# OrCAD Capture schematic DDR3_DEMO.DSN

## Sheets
1 01 POWER: size C; title: MCIMX6Q-SMART DEVICE; rev: A1; company: Freescale Semiconductor; note: SOURCE:SCH-27392 PDF:SPF-27392; note: 6501 William Cannon Drive West; note: Austin, TX 78735-8598
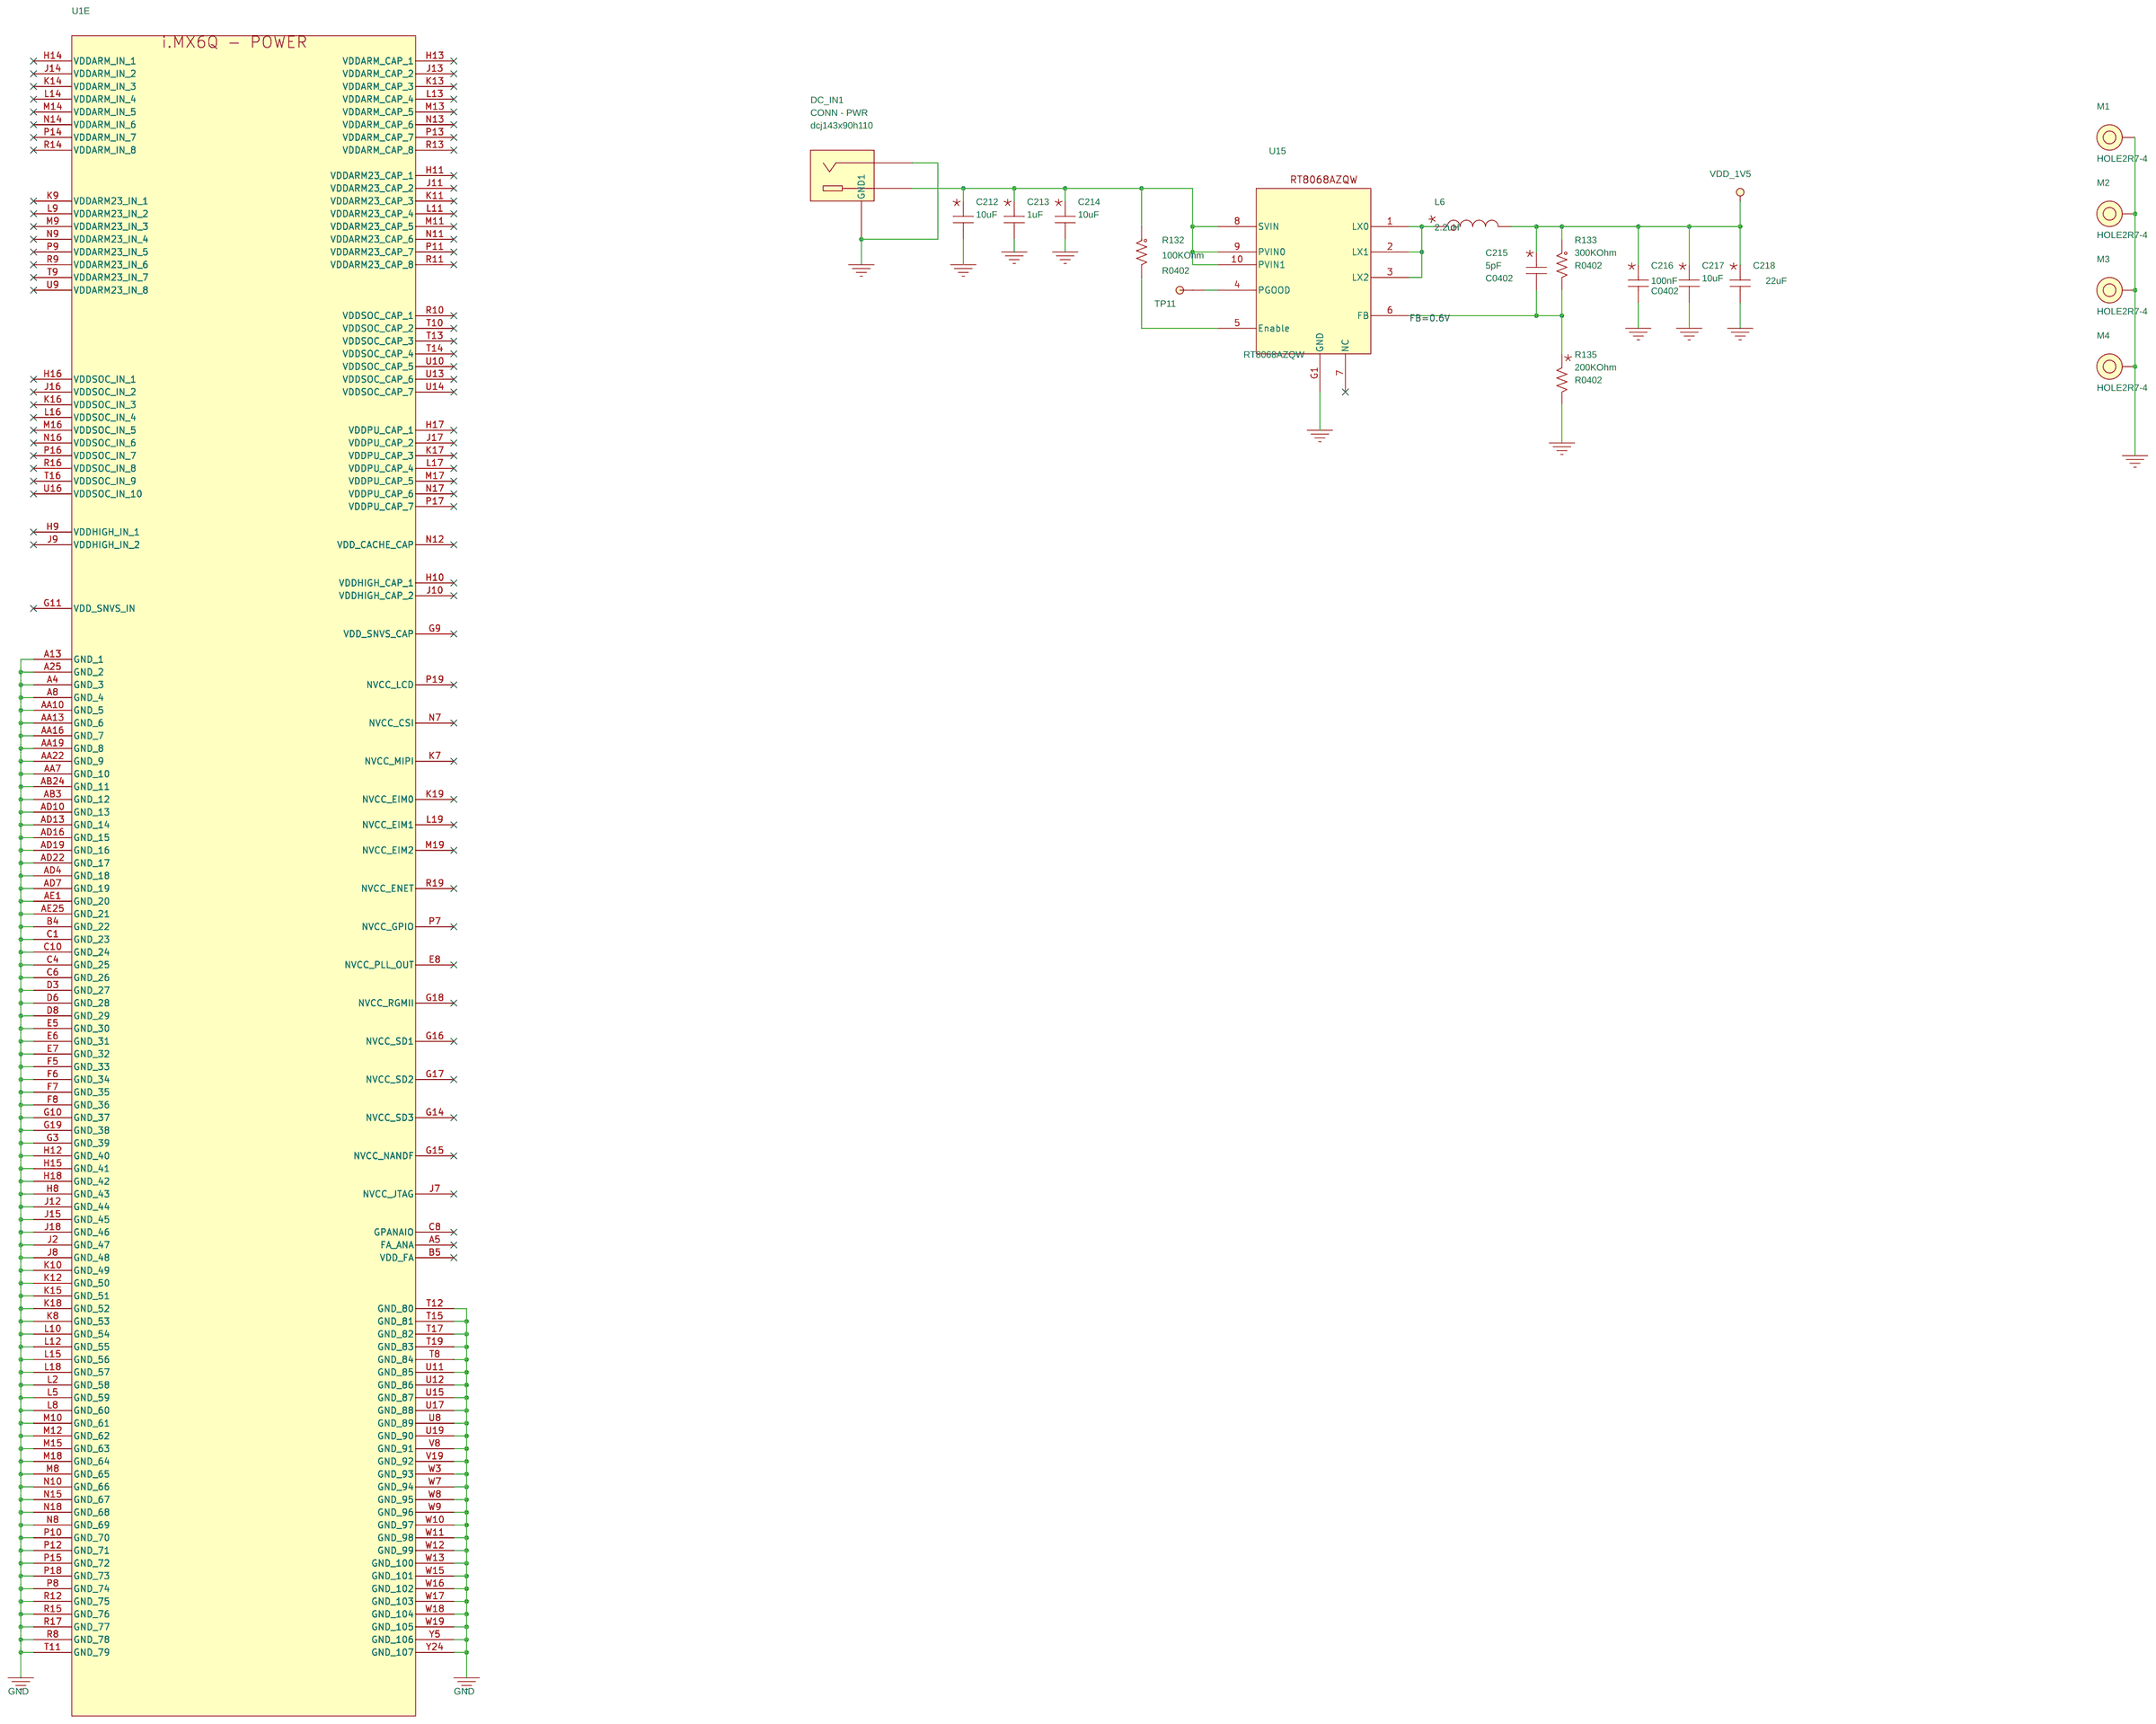
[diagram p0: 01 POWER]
2 02 DDR3 MEMORY: size C; rev: B1
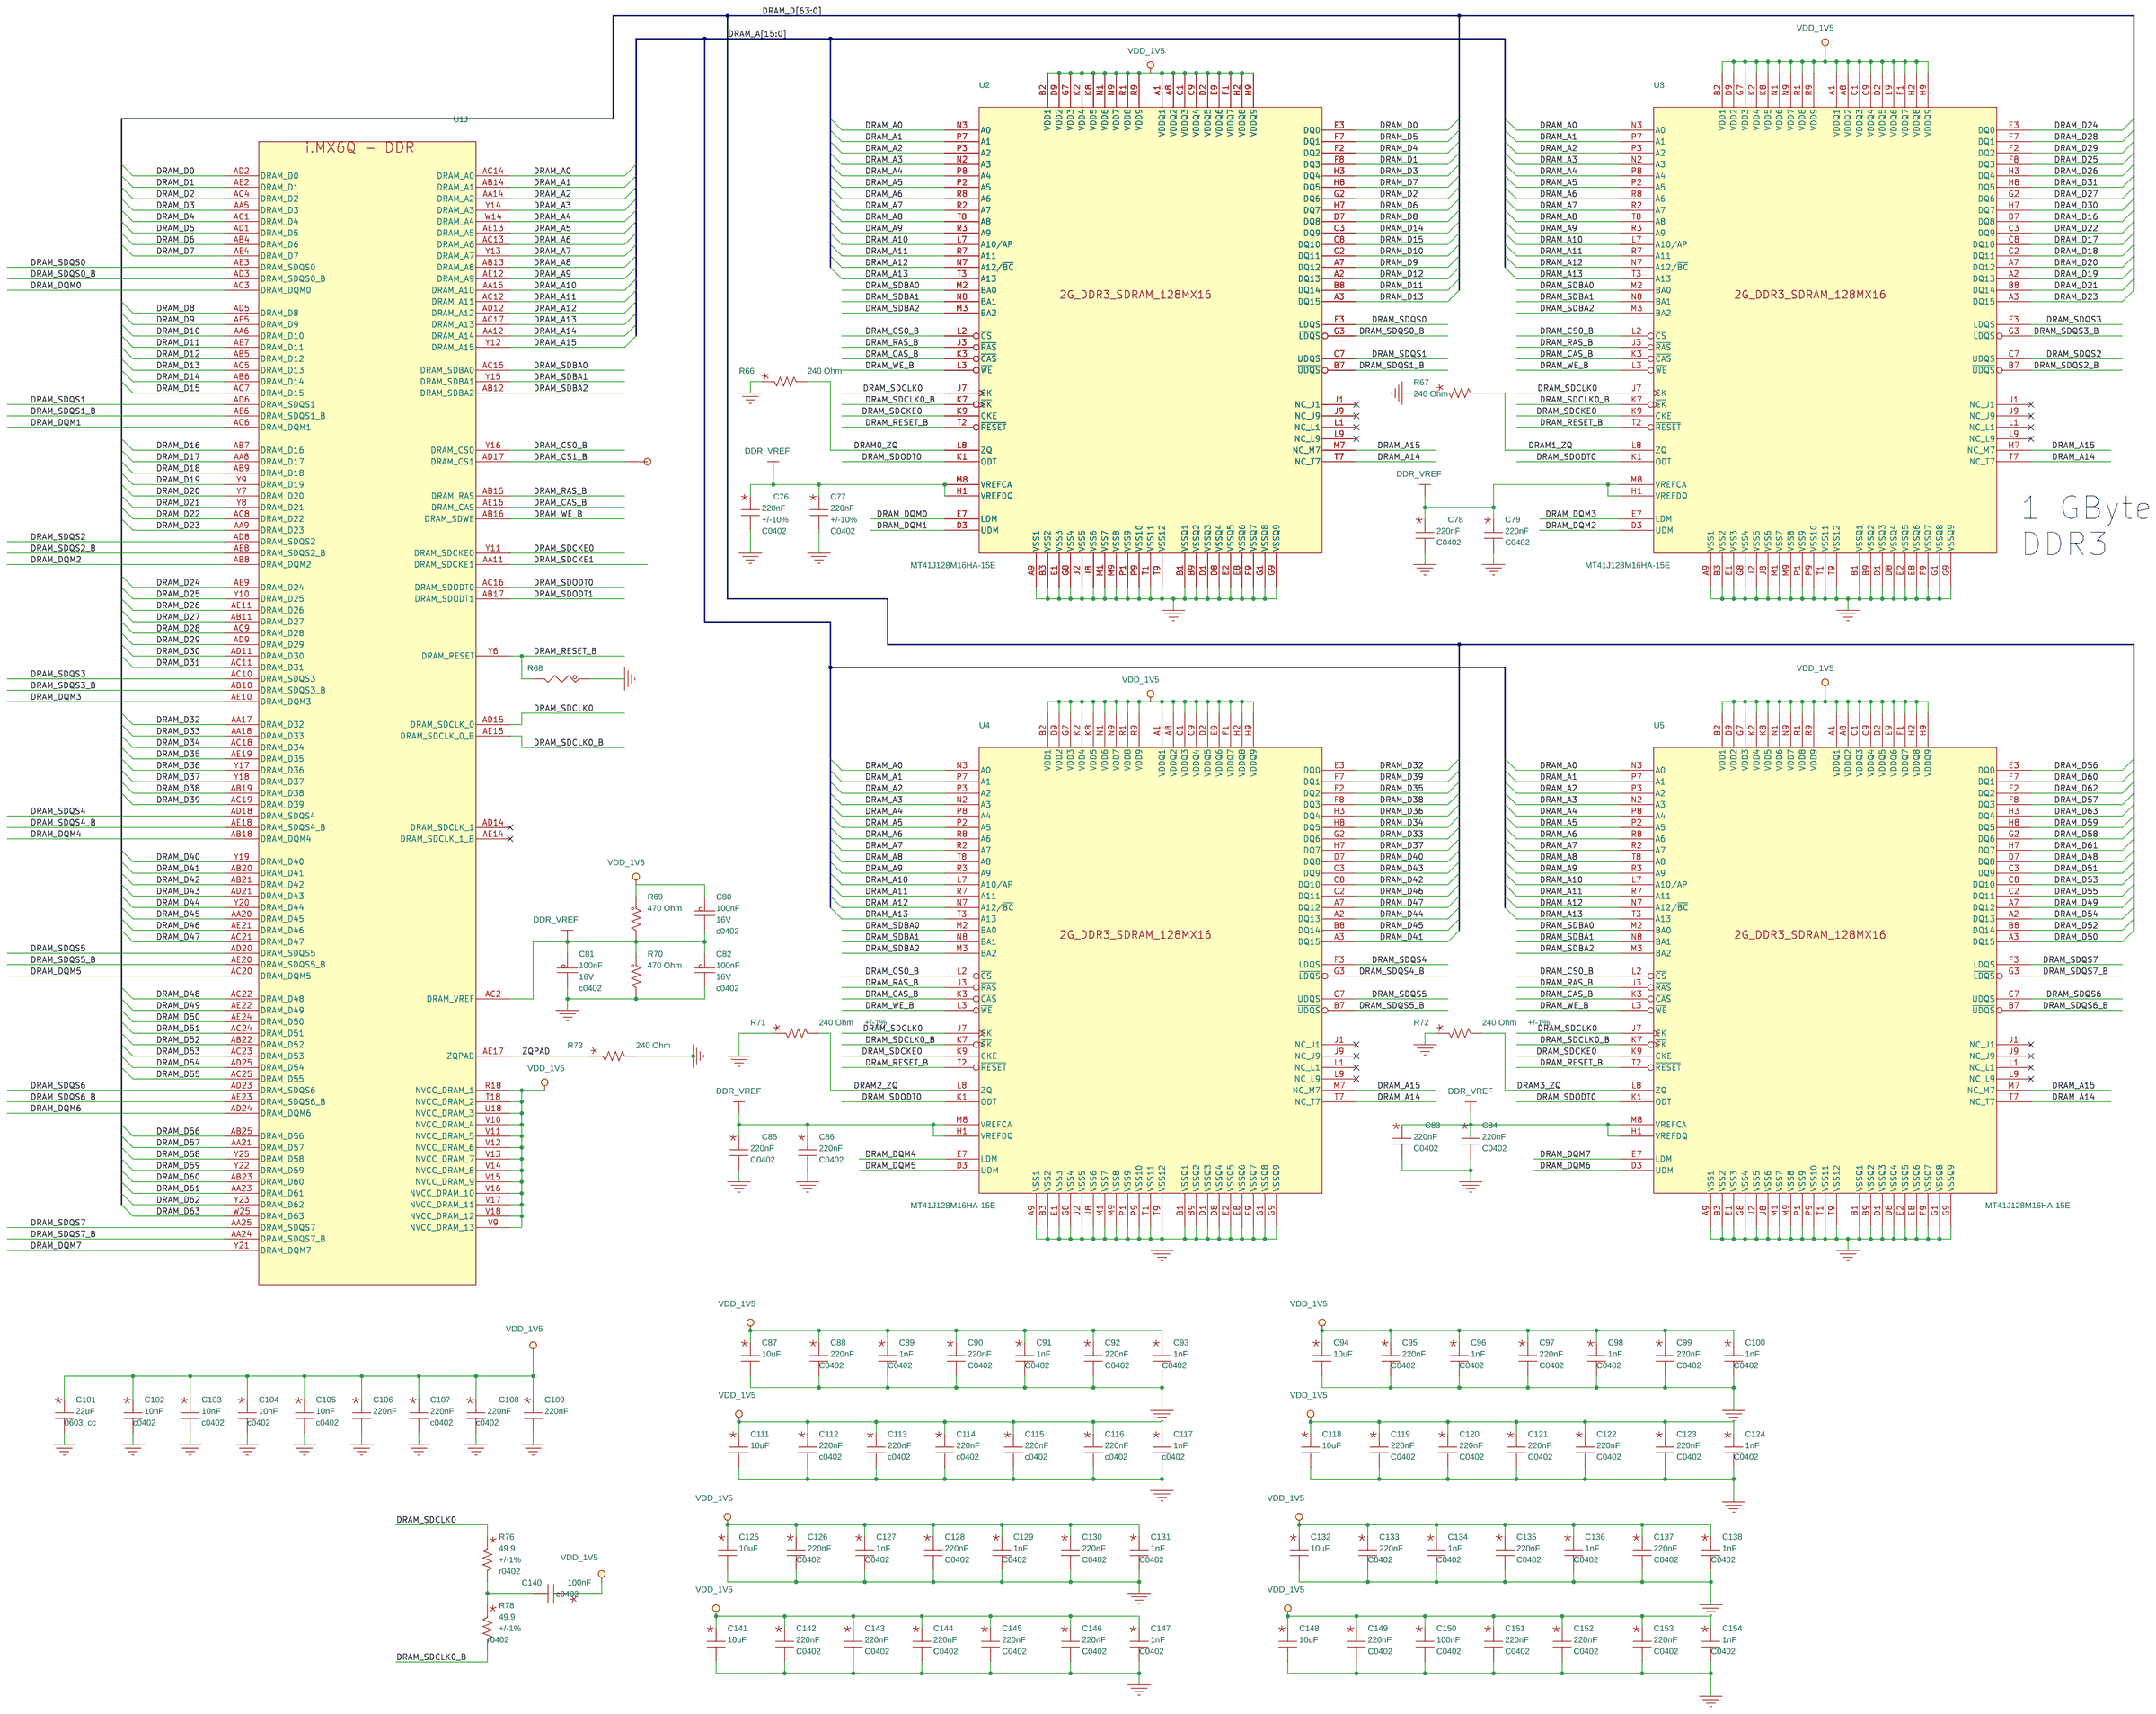
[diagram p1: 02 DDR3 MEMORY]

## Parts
sheet 01 POWER
C212  10uF  [c0603]
C213  1uF  [c0402]
C214  10uF  [c0603]
C215  5pF  [C0402]
C216  100nF  [C0402]
C217  10uF  [c0603]
C218  22uF  [c0805]
DC_IN1  CONN - PWR  [dcj143x90h110]
L6  2.2uH  [l2_5r0x5r0_lqh]
M1  HOLE2R7-4  [HOLE2R7-4]
M2  HOLE2R7-4  [HOLE2R7-4]
M3  HOLE2R7-4  [HOLE2R7-4]
M4  HOLE2R7-4  [HOLE2R7-4]
R132  100KOhm  [R0402]
R133  300KOhm  [R0402]
R135  200KOhm  [R0402]
TP11  TP  [TPC30B]
U1  iMX6Q  [BGA624_0P8_21X21]  (sections E,J)
U15  RT8068AZQW  [dfn11ch8]
sheet 02 DDR3 MEMORY
C76  220nF  [C0402]
C77  220nF  [C0402]
C78  220nF  [C0402]
C79  220nF  [C0402]
C80  100nF  [c0402]
C81  100nF  [c0402]
C82  100nF  [c0402]
C83  220nF  [C0402]
C84  220nF  [C0402]
C85  220nF  [C0402]
C86  220nF  [C0402]
C87  10uF  [c0603]
C88  220nF  [C0402]
C89  1nF  [C0402]
C90  220nF  [C0402]
C91  1nF  [C0402]
C92  220nF  [C0402]
C93  1nF  [C0402]
C94  10uF  [c0603]
C95  220nF  [C0402]
C96  1nF  [C0402]
C97  220nF  [C0402]
C98  1nF  [C0402]
C99  220nF  [C0402]
C100  1nF  [C0402]
C101  22uF  [0603_cc]
C102  10nF  [c0402]
C103  10nF  [c0402]
C104  10nF  [c0402]
C105  10nF  [c0402]
C106  220nF  [c0402]
C107  220nF  [c0402]
C108  220nF  [c0402]
C109  220nF  [c0402]
C111  10uF  [c0402]
C112  220nF  [c0402]
C113  220nF  [c0402]
C114  220nF  [c0402]
C115  220nF  [c0402]
C116  220nF  [c0402]
C117  1nF  [c0402]
C118  10uF  [c0603]
C119  220nF  [C0402]
C120  220nF  [C0402]
C121  220nF  [C0402]
C122  220nF  [C0402]
C123  220nF  [C0402]
C124  1nF  [C0402]
C125  10uF  [c0603]
C126  220nF  [C0402]
C127  1nF  [C0402]
C128  220nF  [C0402]
C129  1nF  [C0402]
C130  220nF  [C0402]
C131  1nF  [C0402]
C132  10uF  [c0603]
C133  220nF  [C0402]
C134  1nF  [C0402]
C135  220nF  [C0402]
C136  1nF  [C0402]
C137  220nF  [C0402]
C138  1nF  [C0402]
C140  100nF  [c0402]
C141  10uF  [c0603]
C142  220nF  [C0402]
C143  220nF  [C0402]
C144  220nF  [C0402]
C145  220nF  [C0402]
C146  220nF  [C0402]
C147  1nF  [C0402]
C148  10uF  [c0603]
C149  220nF  [C0402]
C150  100nF  [C0402]
C151  220nF  [C0402]
C152  220nF  [C0402]
C153  220nF  [C0402]
C154  1nF  [C0402]
R66  240 Ohm  [r0402]
R67  240 Ohm  [r0402]
R68  10K  [r0402]
R69  470 Ohm  [r0402]
R70  470 Ohm  [r0402]
R71  240 Ohm  [r0402]
R72  240 Ohm  [r0402]
R73  240 Ohm  [r0402]
R76  49.9  [r0402]
R78  49.9  [r0402]
TP2  TP  [TPC30B]
U2  MT41J128M16HA-15E  [bga96_0p8_9p15x14p15]
U3  MT41J128M16HA-15E  [bga96_0p8_9p15x14p15]
U4  MT41J128M16HA-15E  [bga96_0p8_9p15x14p15]
U5  MT41J128M16HA-15E  [bga96_0p8_9p15x14p15]

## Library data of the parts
C87 C94 C118 C125 C132 C141 C148 C212 C217 C218 = CC0603MRX5R5BB106: CAP,10uF,+/-20%,X5R,10V,G,SMD0603; Approval Status: E; CCL: for MID; DATASHEET_NUMBER: 55612; Foxconn Part Number: 620112400-023-G; Green State: G; HHPN: STDPN; Item Status : E; Mfg: TAIYO; Mfg Part Number: LMK107BJ106MALTD; ONLY_DATASHEETNAME: YAGEO_CC0603MRX5R5BB106_DS.pdf; Package Type: SMD; Package Type : SMD; Part Number: 62010L000-011-G; Part Type: RoHS\Capacitor\MLCC; RELATED_PARTS: http://ytpdm.efoxconn.com/Windchill/netmarkets/jsp/ext/ytpdm/bom/cis/searchManufacturePart1.jsp?strVPartNumber=62010L000-VPN-G; Relex Category: 4; Relex Subcategory: 3; Remark: Reserved; Sub System: Reserved; Supplier P/N : LMK107BJ106MALTD; Tolerance: 6.3V,X5R,+/-20%; VPN: 620112400-VPN-G
C213 = CAP: CAP,1uF,+/-10%,X5R,10V,G,SMD0402; Approval Status: E; CCL: G; Foxconn Part Number: 62010JJ00-015-G; HHPN: 62-01020084-00-015; Item Status : E; KEYID: 20050721-82649; Mfg: MURATA; Mfg Part Number: GRM155R61A105K; ONLY_DATASHEETNAME: MURATA_GRM155R60J105KE19D_DS.pdf; PCB_FOOTPRINT_BEFORE: c0402h5; Package Type: SMD; Package Type : SMD; Part Number: 62-01020084-00-015; Part Type: RoHS\Capacitor\MLCC; RELATED_PARTS: http://ytpdm.efoxconn.com/Windchill/netmarkets/jsp/ext/ytpdm/bom/cis/searchManufacturePart1.jsp?strVPartNumber=62010BN00-VPN-G; Relex Category: 4; Relex Subcategory: 1; Remark: Reserved; Sub System: Reserved; Supplier P/N : GRM155R61A105K; Tolerance: 6.3V,X5R,+/-10%; VPN: 62010JJ00-VPN-G
C214 = GRM188R60J475K: CAP,4.7uF,+/-10%,X5R,6.3V,G,SMD0603; Approval Status: A; CCL: LF; CD: 5; CR6: 5; Foxconn Part Number: 62010BP00-015-G; Green State: C5; HG: 5; HHPN: 62-01020086-00-015; Item Status : A; Mfg: MURATA; ONLY_DATASHEETNAME: MURATA_GRM188R60J475K_DS.pdf; PB: 5; PBB: 5; PBDE: 5; PCB_FOOTPRINT_BEFORE: c0603h8; Package Type: SMD; Package Type : SMD; Part Number: 62-01020086-00-015; Part Type: VPN\ROHS\Capacitor\MLCC; RELATED_PARTS: http://ytpdm.efoxconn.com/Windchill/netmarkets/jsp/ext/ytpdm/bom/cis/searchManufacturePart1.jsp?strVPartNumber=62010BP00-VPN-G; Relex Category: 4; Relex Subcategory: 1; Remark: Reserved; Sub System: Reserved; Tolerance: +/-10%; VPN: 62010BP00-VPN-G; Value : 4.7uF
C215 = CAP: CAP,5pF,+/-0.25pF,NPO(C0G),25V,G,SMD0201; Approval Status: E; CCL: G; DATASHEET_NUMBER: 0000159154; Foxconn Part Number: 62011SB00-015-G; Green State: G; HHPN: STDPN; Item Status : E; KEYID: 20070118-16031; Mfg: MURATA; Mfg Part Number: GRM0335C1E5R0CD01D; ONLY_DATASHEETNAME: MURATA_GRM1555C1H5R0C_DS.pdf; Package Type: SMD; Package Type : SMD; Part Number: GRM1555C1H5R0C; Part Type: RoHS\Capacitor\MLCC; RELATED_PARTS: http://ytpdm.efoxconn.com/Windchill/netmarkets/jsp/ext/ytpdm/bom/cis/searchManufacturePart1.jsp?strVPartNumber=62010UD00-VPN-G; Relex Category: 4; Remark: Reserved; Sub System: Reserved; Supplier P/N : GRM0335C1E5R0CD01D; Tolerance: +/-0.25pF; VPN: 62011SB00-VPN-G
C216 = CAP: CAP,100nF,+/-10%,X5R,10V,G,SMD0201; Approval Status: A; CD: 100; CR6: 1000; Foxconn Part Number: 620112U00-011-G; Green State: C5; HG: 1000; HHPN: 62-01030380-00-011-G; Item Status : A; KEYID: 1667; Mfg: YAGEO; Mfg Part Number: CC0201KRX5R6BB104; ONLY_DATASHEETNAME: MLCC.pdf; PB: 1000; PBB: 1000; PBDE: 1000; Package Type: SMD; Package Type : SMD; Part Number: 62-01030380-00-011; Part Type: VPN\ROHS\Capacitor\MLCC; RELATED_PARTS: http://ytpdm.efoxconn.com/Windchill/netmarkets/jsp/ext/ytpdm/bom/cis/searchManufacturePart1.jsp?strVPartNumber=620101T00-VPN-G; Relex Category: 4; Relex Subcategory: 3; Remark: Reserved; Sub System: Reserved; Supplier P/N : CC0201KRX5R6BB104; Tolerance: 16V, X7R, +/-10%; VPN: 620112U00-VPN-G
DC_IN1 = JPD1021-NB751-7F_0: CONN,I/O,Power Jack,R/A,Bla,G/F,G,DIP-3; Approval Status: E; CCL: G; Foxconn Part Number: 340415U00-H59-G; Green State: G; HHPN: STDPN; Mfg: SINGATRON; Mfg Part Number: 2DC-G213I200; Only Datasheet Name: FOXCONN_JPD1021-NB751-7F_DS.pdf; Package Type: DIP; Part Number: 340415600-600-G; Part Type: RoHS\Connector\I/O Port; Relex Category: 9; Relex Subcategory: 1; Remark: @DCIN; Sub System: Reserved; Tolerance: <Tolerance>; VPN: 340415U00-H59-G; Datasheet: http://pdm-dmd.pdm.foxconn.com/cis/MB/Dell/Datasheet/FOXCONN_JPD1021-NB751-7F_DS.pdf
L6 = PCMB042T-2R2MS_0: IND,2.2uH@100KHz,+/-30%,2.6A,36mOhm,SHLD,G,SMD; Approval Status: E; CCL: for MID; DATASHEET_NUMBER: 55499; Foxconn Part Number: 63033K000-015-G; Green State: G; HHPN: STDPN; Item Status : E; Mfg: MURATA; Mfg Part Number: LQH5BPN2R2NT0L; ONLY_DATASHEETNAME: CYNTEC_PCMB042T-2R2MS_DS.pdf; Package Type: SMD; Package Type : SMD; Part Number: 63031HQ00-034-G; Part Type: RoHS\Inductor\SMD Power Inductor; RELATED_PARTS: http://ytpdm.efoxconn.com/Windchill/netmarkets/jsp/ext/ytpdm/bom/cis/searchManufacturePart1.jsp?strVPartNumber=63031HQ00-VPN-G; Relex Category: 5; Relex Subcategory: 2; Remark: Reserved; Sub System: Reserved; Supplier P/N : LQH5BPN2R2NT0L; Tolerance: +/-20%; VPN: 63033K000-VPN-G
M1-M4 = MNTHOLE_3.2
R132 = RC0201JR-07100KL: RES,100KOhm,+/-1%,1/20W,G,SMD0201; Approval Status: E; CCL: G; DATASHEET_NUMBER: 291759; Foxconn Part Number: 61011E300-011-G; Green State: G; HHPN: STDPN; Item Status : E; Mfg: YAGEO; Mfg Part Number: RC0201FR-07100KL; ONLY_DATASHEETNAME: YAGEO_RC0201JR-07100KL_DS.rar; Package Type: SMD; Package Type : SMD; Part Number: 61011ES00-011-G; Part Type: RoHS\Resistor\Chip Resistor; RELATED_PARTS: http://ytpdm.efoxconn.com/Windchill/netmarkets/jsp/ext/ytpdm/bom/cis/searchManufacturePart1.jsp?strVPartNumber=61011ES00-VPN-G; Relex Category: 3; Relex Subcategory: 2; Remark: Reserved; Sub System: Reserved; Supplier P/N : RC0201FR-07100KL; Tolerance: +/-1%
R133 = RC0402FR-07150KL: RES,300KOhm,+/-1%,1/20W,G,SMD0201; Approval Status: E; CCL: RoHS; CD: 100; CR6: 1000; DATASHEET_NUMBER: 81926; Foxconn Part Number: 61012W600-011-G; Green State: C5; HG: 1000; HHPN: 61-01002463-01-011; Item Status : E; KEYID: 20060609-111810; Mfg: YAGEO; Mfg Part Number: RC0201FR-07300KL; ONLY_DATASHEETNAME: YAGEO_RC0402FR_07150KL_DS.pdf; PB: 1000; PBB: 1000; PBDE: 1000; PCB_FOOTPRINT_BEFORE: r0402h4; Package Type: SMD; Package Type : SMD; Part Number: 61-01002463-01-011; Part Type: VPN\ROHS\Resistor\Chip Resistor; RELATED_PARTS: http://ytpdm.efoxconn.com/Windchill/netmarkets/jsp/ext/ytpdm/bom/cis/searchManufacturePart1.jsp?strVPartNumber=610116G00-VPN-G; Relex Category: 3; Relex Subcategory: 2; Remark: Reserved; Sub System: Reserved; Supplier P/N : RC0201FR-07300KL; Tolerance: +/-1%; VPN: 61012W600-VPN-G
R135 = RC0402FR-07100KL: RES,200KOhm,+/-1%,1/20W,G,SMD0201; Approval Status: E; CCL: G; CD: 100; CR6: 1000; Foxconn Part Number: 61011VW00-011-G; Green State: C5; HG: 1000; HHPN: 61-01000550-03-011-G; Item Status : E; KEYID: 20051019-14316; Mfg: YAGEO; Mfg Part Number: RC0201FR-07200KL; ONLY_DATASHEETNAME: YAGEO_RC0402FR_07100KL_DS.pdf; PB: 1000; PBB: 1000; PBDE: 1000; PCB_FOOTPRINT_BEFORE: r0402h4; Package Type: SMD; Package Type : SMD; Part Number: 61-01000550-03-011-G; Part Type: VPN\ROHS\Resistor\Chip Resistor; RELATED_PARTS: http://ytpdm.efoxconn.com/Windchill/netmarkets/jsp/ext/ytpdm/bom/cis/searchManufacturePart1.jsp?strVPartNumber=61010L100-VPN-G; Relex Category: 3; Relex Subcategory: 2; Remark: Reserved; Sub System: Reserved; Supplier P/N : RC0201FR-07200KL; Tolerance: +/-1%; VPN: 61011VW00-VPN-G
TP2 TP11 = TP_0: TEST POINT; Critical_Part: No; Part Number: Waiting Foxconn Part Number; QVL_Approve: None; Remark: Dummy; Vendor: Waiting
U1 = PCIMX6Q6VV1A_0: IC MCU MX6QUAD ARM CORTEX-A9 FCLBGA624; AGILE_PN: 344-01218; CAD_APPROVED: Yes; HEIGHT: 2.16MM; MFG_NAME01: FREESCALE SEMICONDUCTOR; MFG_PN01: PCIMX6Q0AVT01A; ROHS: Yes
U15 = RT9199PSP_5: IC,Regulator,RT8068AZQW,3A,1MHZ,G,WDFN-10,SMD; Approval Status: E; CCL: G; CD: 100; CR6: 1000; Foxconn Part Number: 32012EL00-264-G; Green State: C6; HG: 1000; HHPN: 32-09400062-00; Item Status : E; KEYID: 20060510-112323; Mfg: RICHTEK; ONLY_DATASHEETNAME: RICHTEK_RT9199PSP_DS.pdf; PB: 1000; PBB: 1000; PBDE: 1000; Package Type: SMD; Package Type : SMD; Part Number: 32-09400062-00; Part Type: ROHS\IC\Linear IC; RELATED_PARTS: http://ytpdm.efoxconn.com/Windchill/netmarkets/jsp/ext/ytpdm/bom/cis/searchManufacturePart1.jsp?strVPartNumber=320109Y00-VPN-G; Relex Category: 1; Relex Subcategory: 3; Remark: Reserved; Sub System: Reserved; VPN: 32012EL00-VPN-G
C76-C79 C83-C86 C109 = CAP: CAP,220nF,+/-20%,X5R,6.3V,G,SMD0201; Approval Status: A; CCL: G; CD: 100; CR6: 1000; DATASHEET_NUMBER: 0000175265; Foxconn Part Number: 620115S00-015-G; Green State: C5; HG: 1000; HHPN: STDPN; KEYID: 20070321-51853; Mfg: MURATA; Mfg Part Number: GRM033R60J224ME15D; ONLY_DATASHEETNAME: YAGEO_CC0603KRX7R7BB224_DS.pdf; PB: 1000; PBB: 1000; PBDE: 1000; Package Type: SMD; Part Number: 62010KD00-011-G; Part Type: VPN\ROHS\Capacitor\MLCC; RELATED_PARTS: http://ytpdm.efoxconn.com/Windchill/netmarkets/jsp/ext/ytpdm/bom/cis/searchManufacturePart1.jsp?strVPartNumber=62010KD00-VPN-G; Relex Category: 4; Relex Subcategory: 3; Remark: Reserved; Sub System: Reserved; Supplier : MURATA; Tolerance: +/-10%; VPN: 620115S00-VPN-G
C80-C82 = CAP_NP: CAP CER 0.1UF 16V 10% X7R 0402; AGILE_PN: 150-75182; CAD_APPROVED: Yes; FPLIST: CC0402_25,CC0402_HD,0402_CC; HEIGHT: 0.635MM; MFG_NAME01: KEMET; MFG_PN01: C0402C104K4RAC; PRIORITY_PN: 021-00274; ROHS: Yes; SIGNAL_MODEL: DEFAULT_CAPACITOR_100000pF_2_1; Tolerance: 10%; WVDC: 16V
C88 C92 C95 C99 C112 C115 C116 C119 C122 C123 C126 C130 C133 C137 C142 C145 C146 C149 C152 C153 = CAP: CAP,100nF,+/-10%,X5R,10V,G,SMD0201; Approval Status: A; CD: 100; CR6: 1000; Foxconn Part Number: 620112U00-011-G; Green State: C5; HG: 1000; HHPN: 62-01030380-00-011-G; KEYID: 1667; Mfg: YAGEO; Mfg Part Number: CC0201KRX5R6BB104; ONLY_DATASHEETNAME: MLCC.pdf; PB: 1000; PBB: 1000; PBDE: 1000; Package Type: SMD; Part Number: 62-01030380-00-011; Part Type: VPN\ROHS\Capacitor\MLCC; RELATED_PARTS: http://ytpdm.efoxconn.com/Windchill/netmarkets/jsp/ext/ytpdm/bom/cis/searchManufacturePart1.jsp?strVPartNumber=620101T00-VPN-G; Relex Category: 4; Relex Subcategory: 3; Remark: Reserved; Sub System: Reserved; Supplier : YAGEO; Tolerance: 16V, X7R, +/-10%; VPN: 620112U00-VPN-G
C89 C96 C127 C134 = CAP: CAP,1nF,+/-10%,X7R,25V,G,SMD0402; Approval Status: A; CD: 100; CR6: 1000; Foxconn Part Number: 62010LF00-011-G; Green State: C5; HG: 1000; HHPN: 62-01030114-00-011-G; KEYID: 1705; Mfg: YAGEO; Mfg Part Number: CC0201KRX7R8BB102; ONLY_DATASHEETNAME: MLCC.pdf; PB: 1000; PBB: 1000; PBDE: 1000; Package Type: SMD; Part Number: 62-01030114-00-011; Part Type: VPN\ROHS\Capacitor\MLCC; RELATED_PARTS: http://ytpdm.efoxconn.com/Windchill/netmarkets/jsp/ext/ytpdm/bom/cis/searchManufacturePart1.jsp?strVPartNumber=620103K00-VPN-G; Relex Category: 4; Relex Subcategory: 3; Remark: Reserved; Sub System: Reserved; Supplier : YAGEO; Tolerance: 50V, X7R, +/-10%; VPN: 62010LF00-VPN-G
C90 C97 C128 C135 = CAP: CAP,100nF,+/-10%,X5R,10V,G,SMD0201; Approval Status: A; CD: 100; CR6: 1000; Foxconn Part Number: 620112U00-011-G; Green State: C5; HG: 1000; HHPN: 62-01030380-00-011-G; KEYID: 1667; Mfg: YAGEO; Mfg Part Number: CC0201KRX5R6BB104; ONLY_DATASHEETNAME: MLCC.pdf; PB: 1000; PBB: 1000; PBDE: 1000; Package Type: SMD; Part Number: 62-01030380-00-011; Part Type: VPN\ROHS\Capacitor\MLCC; RELATED_PARTS: http://ytpdm.efoxconn.com/Windchill/netmarkets/jsp/ext/ytpdm/bom/cis/searchManufacturePart1.jsp?strVPartNumber=620101T00-VPN-G; Relex Category: 4; Relex Subcategory: 3; Remark: Dummy; Sub System: Rserved; Supplier : YAGEO; Tolerance: 16V, X7R, +/-10%; VPN: 620112U00-VPN-G
C91 C98 C129 C136 = CAP: CAP,1nF,+/-10%,X7R,25V,G,SMD0201; Approval Status: A; CD: 100; CR6: 1000; Foxconn Part Number: 62010LF00-011-G; Green State: C5; HG: 1000; HHPN: 62-01030114-00-011-G; Item Status : A; KEYID: 1705; Mfg: YAGEO; Mfg Part Number: CC0201KRX7R8BB102; ONLY_DATASHEETNAME: MLCC.pdf; PB: 1000; PBB: 1000; PBDE: 1000; Package Type: SMD; Package Type : SMD; Part Number: 62-01030114-00-011; Part Type: VPN\ROHS\Capacitor\MLCC; RELATED_PARTS: http://ytpdm.efoxconn.com/Windchill/netmarkets/jsp/ext/ytpdm/bom/cis/searchManufacturePart1.jsp?strVPartNumber=620103K00-VPN-G; Relex Category: 4; Relex Subcategory: 3; Remark: Reserved; Sub System: Rserved; Supplier P/N : CC0201KRX7R8BB102; Tolerance: 50V, X7R, +/-10%; VPN: 62010LF00-VPN-G
C93 C100 C117 C124 C131 C138 C147 C154 = CAP: CAP,1nF,+/-10%,X7R,25V,G,SMD0201; Approval Status: A; CD: 100; CR6: 1000; Foxconn Part Number: 62010LF00-011-G; Green State: C5; HG: 1000; HHPN: 62-01030114-00-011-G; KEYID: 1705; Mfg: YAGEO; Mfg Part Number: CC0201KRX7R8BB102; ONLY_DATASHEETNAME: MLCC.pdf; PB: 1000; PBB: 1000; PBDE: 1000; Package Type: SMD; Part Number: 62-01030114-00-011; Part Type: VPN\ROHS\Capacitor\MLCC; RELATED_PARTS: http://ytpdm.efoxconn.com/Windchill/netmarkets/jsp/ext/ytpdm/bom/cis/searchManufacturePart1.jsp?strVPartNumber=620103K00-VPN-G; Relex Category: 4; Relex Subcategory: 3; Remark: Reserved; Sub System: Reserved; Supplier : YAGEO; Tolerance: 50V, X7R, +/-10%; VPN: 62010LF00-VPN-G
C101 = CAP: CAP CER 22UF 4V 20% X5R 0603; Approval Status: A; CD: 5; CR6: 5; Foxconn Part Number: 620108H00-015-G; Green State: C5; HG: 5; HHPN: 62-01020059-00-015-G; Item Status : A; KEYID: 20050824-04221; Mfg: MURATA; Mfg Part Number: GRM21BR60J226M; ONLY_DATASHEETNAME: MURATA_GRM21BR60J226ME39L_DS.pdf; PB: 5; PBB: 5; PBDE: 5; PCB_FOOTPRINT_BEFORE: c0805h14; Package Type: SMD; Package Type : SMD; Part Number: 62-01020059-00-015; Part Type: VPN\ROHS\Capacitor\MLCC; RELATED_PARTS: http://ytpdm.efoxconn.com/Windchill/netmarkets/jsp/ext/ytpdm/bom/cis/searchManufacturePart1.jsp?strVPartNumber=620108H00-VPN-G; Relex Category: 4; Relex Subcategory: 1; Remark: Reserved; Sub System: Reserved; Supplier P/N : GRM21BR60J226M; Tolerance: 6.3V,X5R,+/-20%; VPN: 620108H00-VPN-G
C102 C103 = GRM155R71H103K: CAP,10nF,+/-10%,X7R,10V,G,SMD0201; Approval Status: E; CCL: G; DATASHEET_NUMBER: 0000246316; Footprint : C0201; Foxconn Part Number: 62010LA00-011-G; Green State: G; HHPN: STDPN; KEYID: 20071225-23718; Mfg: YAGEO; Mfg Part Number: CC0201KRX7R6BB103; ONLY_DATASHEETNAME: MURATA_GRM155R71H103K_DS.pdf; Package Type: SMD; Part Number: 62010QB00-015-G; Part Type: RoHS\Capacitor\MLCC; RELATED_PARTS: http://ytpdm.efoxconn.com/Windchill/netmarkets/jsp/ext/ytpdm/bom/cis/searchManufacturePart1.jsp?strVPartNumber=62010QB00-VPN-G; Relex Category: 4; Relex Subcategory: 2; Remark: Reserved; Sub System: Reserved; Supplier : YAGEO; Tolerance: +/-10%; VPN: 62010LA00-VPN-G
C104 = GRM155R71H103K: CAP,10nF,+/-10%,X7R,10V,G,SMD0201; Approval Status: E; CCL: G; DATASHEET_NUMBER: 0000246316; Footprint : C0201; Foxconn Part Number: 62010LA00-011-G; Green State: G; HHPN: STDPN; KEYID: 20071225-23718; Mfg: YAGEO; Mfg Part Number: CC0201KRX7R6BB103; ONLY_DATASHEETNAME: MURATA_GRM155R71H103K_DS.pdf; Package Type: SMD; Part Number: 62010QB00-015-G; Part Type: RoHS\Capacitor\MLCC; RELATED_PARTS: http://ytpdm.efoxconn.com/Windchill/netmarkets/jsp/ext/ytpdm/bom/cis/searchManufacturePart1.jsp?strVPartNumber=62010QB00-VPN-G; Relex Category: 4; Relex Subcategory: 2; Sub System: Reserved; Supplier : YAGEO; Tolerance: +/-10%; VPN: 62010LA00-VPN-G
C105 = GRM155R71H103K: CAP,10nF,+/-10%,X7R,10V,G,SMD0201; Approval Status: E; CCL: G; Footprint : C0201; Green State: G; HHPN: STDPN; Mfg: YAGEO; Mfg Part Number: CC0201KRX7R6BB103; ONLY_DATASHEETNAME: MURATA_GRM155R71H103K_DS.pdf; Package Type: SMD; Part Number: 62010QB00-015-G; Part Type: RoHS\Capacitor\MLCC; RELATED_PARTS: http://ytpdm.efoxconn.com/Windchill/netmarkets/jsp/ext/ytpdm/bom/cis/searchManufacturePart1.jsp?strVPartNumber=62010QB00-VPN-G; Relex Category: 4; Relex Subcategory: 2; Sub System: Reserved; Supplier : YAGEO; Tolerance: +/-10%
C106 = CAP: CAP,220nF,+/-20%,X5R,6.3V,G,SMD0201; Approval Status: A; CCL: G; CD: 100; CR6: 1000; DATASHEET_NUMBER: 0000175265; Foxconn Part Number: 620115S00-015-G; Green State: C5; HG: 1000; HHPN: STDPN; KEYID: 20070321-51853; Mfg: MURATA; Mfg Part Number: GRM033R60J224ME15D; ONLY_DATASHEETNAME: YAGEO_CC0603KRX7R7BB224_DS.pdf; PB: 1000; PBB: 1000; PBDE: 1000; Package Type: SMD; Part Number: 62010KD00-011-G; Part Type: VPN\ROHS\Capacitor\MLCC; RELATED_PARTS: http://ytpdm.efoxconn.com/Windchill/netmarkets/jsp/ext/ytpdm/bom/cis/searchManufacturePart1.jsp?strVPartNumber=62010KD00-VPN-G; Relex Category: 4; Relex Subcategory: 3; Sub System: Reserved; Supplier : MURATA; Tolerance: +/-10%; VPN: 620115S00-VPN-G
C107 C108 = CAP: CAP,220nF,+/-20%,X5R,6.3V,G,SMD0201; Approval Status: A; CCL: G; CD: 100; CR6: 1000; DATASHEET_NUMBER: 0000175265; Footprint : C0201; Foxconn Part Number: 620115S00-015-G; Green State: C5; HG: 1000; HHPN: STDPN; KEYID: 20070321-51853; Mfg: MURATA; Mfg Part Number: GRM033R60J224ME15D; ONLY_DATASHEETNAME: YAGEO_CC0603KRX7R7BB224_DS.pdf; PB: 1000; PBB: 1000; PBDE: 1000; Package Type: SMD; Part Number: 62010KD00-011-G; Part Type: VPN\ROHS\Capacitor\MLCC; RELATED_PARTS: http://ytpdm.efoxconn.com/Windchill/netmarkets/jsp/ext/ytpdm/bom/cis/searchManufacturePart1.jsp?strVPartNumber=62010KD00-VPN-G; Relex Category: 4; Relex Subcategory: 3; Remark: Reserved; Sub System: Reserved; Supplier : MURATA; Tolerance: +/-10%; VPN: 620115S00-VPN-G
C111 = CC0603MRX5R5BB106: CAP,10uF,+/-20%,X5R,10V,G,SMD0603; Approval Status: E; CCL: for MID; DATASHEET_NUMBER: 55612; Footprint : c0603; Foxconn Part Number: 620112400-023-G; Green State: G; HHPN: STDPN; Item Status : E; Mfg: TAIYO; Mfg Part Number: LMK107BJ106MALTD; ONLY_DATASHEETNAME: YAGEO_CC0603MRX5R5BB106_DS.pdf; Package Type: SMD; Package Type : SMD; Part Number: 62010L000-011-G; Part Type: RoHS\Capacitor\MLCC; RELATED_PARTS: http://ytpdm.efoxconn.com/Windchill/netmarkets/jsp/ext/ytpdm/bom/cis/searchManufacturePart1.jsp?strVPartNumber=62010L000-VPN-G; Relex Category: 4; Relex Subcategory: 3; Remark: Reserved; Sub System: Reserved; Supplier P/N : LMK107BJ106MALTD; Tolerance: 6.3V,X5R,+/-20%; VPN: 620112400-VPN-G
C113 C114 C120 C121 C143 C144 C150 C151 = CAP: CAP,100nF,+/-10%,X5R,10V,G,SMD0201; Approval Status: A; CD: 100; CR6: 1000; Foxconn Part Number: 620112U00-011-G; Green State: C5; HG: 1000; HHPN: 62-01030380-00-011-G; KEYID: 1667; Mfg: YAGEO; Mfg Part Number: CC0201KRX5R6BB104; ONLY_DATASHEETNAME: MLCC.pdf; PB: 1000; PBB: 1000; PBDE: 1000; Package Type: SMD; Part Number: 62-01030380-00-011; Part Type: VPN\ROHS\Capacitor\MLCC; RELATED_PARTS: http://ytpdm.efoxconn.com/Windchill/netmarkets/jsp/ext/ytpdm/bom/cis/searchManufacturePart1.jsp?strVPartNumber=620101T00-VPN-G; Relex Category: 4; Relex Subcategory: 3; Remark: Reserved; Sub System: Rserved; Supplier : YAGEO; Tolerance: 16V, X7R, +/-10%; VPN: 620112U00-VPN-G
C140 = CAP: CAP,100nF,+/-10%,X5R,10V,G,SMD0201; Approval Status: A; CD: 100; CR6: 1000; Footprint : C0201; Foxconn Part Number: 620112U00-011-G; Green State: C5; HG: 1000; HHPN: 62-01030380-00-011-G; Item Status : A; KEYID: 1667; Mfg: YAGEO; Mfg Part Number: CC0201KRX5R6BB104; ONLY_DATASHEETNAME: MLCC.pdf; PB: 1000; PBB: 1000; PBDE: 1000; Package Type: SMD; Package Type : SMD; Part Number: 62-01030380-00-011; Part Type: VPN\ROHS\Capacitor\MLCC; RELATED_PARTS: http://ytpdm.efoxconn.com/Windchill/netmarkets/jsp/ext/ytpdm/bom/cis/searchManufacturePart1.jsp?strVPartNumber=620101T00-VPN-G; Relex Category: 4; Relex Subcategory: 3; Remark: Reserved; Sub System: Reserved; Supplier P/N : CC0201KRX5R6BB104; Tolerance: 16V, X7R, +/-10%; VPN: 620112U00-VPN-G
R66 R67 R71-R73 = RC0402FR-07240RL: RES,240 Ohm,+/-1%,1/20W,G,SMD0201; Approval Status: E; CCL: G; CD: 2; CR6: 2; DATASHEET_NUMBER: 0000245957; Foxconn Part Number: 610135N00-011-G; Green State: C2; HG: 2; HHPN: STDPN; KEYID: 20071222-91056; Mfg: YAGEO; Mfg Part Number: RC0201FR-07240RL; ONLY_DATASHEETNAME: YAGEO_RC0402FR-07240RL_DS.pdf; PB: 230316.6; PBB: 5; PBDE: 5; Package Type: SMD; Part Number: 61011T800-011-G; Part Type: RoHS\Resistor\Chip Resistor; RELATED_PARTS: http://ytpdm.efoxconn.com/Windchill/netmarkets/jsp/ext/ytpdm/bom/cis/searchManufacturePart1.jsp?strVPartNumber=61011T800-VPN-G; Relex Category: 3; Relex Subcategory: 1; Remark: Reserved; Sub System: Reserved; Supplier : YAGEO; Tolerance: +/-1%; VPN: 610135N00-VPN-G
R68 = RES: RES MF 10.0K 1/16W 1% 0402; AGILE_PN: 470-75416; CAD_APPROVED: Yes; FPLIST: RC0402,rc0402_frs; MFG_NAME01: VISHAY INTERTECHNOLOGY; MFG_PN01: CRCW040210K0FKED; PRIORITY_PN: 006-00552; ROHS: Yes; ROOM: KEYPAD; SIGNAL_MODEL: DEFAULT_RESISTOR_10000OHM_2_1; Tolerance: 1%
R69 R70 = RC0603FR-07470RL: RES,470 Ohm,+/-1%,1/20W,G,SMD0201; Approval Status: E; CCL: LF; CD: 100; CR6: 1000; Foxconn Part Number: 61012RN00-011-G; Green State: C5; HG: 1000; HHPN: 61-01000377-01-011-G; Item Status : E; KEYID: 20060509-81844; Mfg: YAGEO; Mfg Part Number: RC0201FR-07470RL; ONLY_DATASHEETNAME: YAGEO_RC0603FR_07470RL_DS.pdf; PB: 230317; PBB: 1000; PBDE: 1000; PCB_FOOTPRINT_BEFORE: r0603h6; Package Type: SMD; Package Type : SMD; Part Number: 61-01000377-01-011; Part Type: VPN\ROHS\Resistor\Chip Resistor; RELATED_PARTS: http://ytpdm.efoxconn.com/Windchill/netmarkets/jsp/ext/ytpdm/bom/cis/searchManufacturePart1.jsp?strVPartNumber=610104E00-VPN-G; Relex Category: 3; Relex Subcategory: 2; Remark: Reserved; Sub System: Reserved; Supplier P/N : RC0201FR-07470RL; VPN: 61012RN00-VPN-G
R76 R78 = RC0402FR-0749R9L: RES,49.9Ohm,+/-1%,1/20W,G,SMD0201; Approval Status: E; CCL: LF; CD: 100; CR6: 1000; Foxconn Part Number: 61011EM00-011-G; Green State: C5; HG: 1000; HHPN: 61-01000833-02-011-G; Item Status : E; KEYID: 4987; Mfg: YAGEO; Mfg Part Number: RC0201FR-0749R9L; ONLY_DATASHEETNAME: YAGEO-RC0402FR-0749R9L-DS.pdf; PB: 1000; PBB: 1000; PBDE: 1000; Package Type: SMD; Package Type : SMD; Part Number: 61-01000833-02-011; Part Type: VPN\ROHS\Resistor\Chip Resistor; RELATED_PARTS: http://ytpdm.efoxconn.com/Windchill/netmarkets/jsp/ext/ytpdm/bom/cis/searchManufacturePart1.jsp?strVPartNumber=610102700-VPN-G; Relex Category: 3; Relex Subcategory: 2; Remark: Reserved; Sub System: Reserved; Supplier P/N : RC0201FR-0749R9L; Tolerance: +/-1%; VPN: 61011EM00-VPN-G
U2-U5 = 2G_DDR3_SDRAM_128MX16_96P: IC MEM DDR3 SDRAM 2Gb 128MX16 1.5V FBGA96; AGILE_PN: 334-77333; CAD_APPROVED: Yes; HEIGHT: 1.2 MM; MFG_NAME01: MICRON; MFG_PN01: MT41J128M16HA-15E:D; ROHS: Yes

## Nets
GND: C76.2 C77.2 C78.2 C79.2 C81.2 C82.2 C83.2 C84.2 C85.2 C86.2 C87.2 C88.2 C89.2 C90.2 C91.2 C92.2 C93.2 C94.2 C95.2 C96.2 C97.2 C98.2 C99.2 C100.2 C101.2 C102.2 C103.2 C104.2 C105.2 C106.2 C107.2 C108.2 C109.2 C111.2 C112.2 C113.2 C114.2 C115.2 C116.2 C117.2 C118.2 C119.2 C120.2 C121.2 C122.2 C123.2 C124.2 C125.2 C126.2 C127.2 C128.2 C129.2 C130.2 C131.2 C132.2 C133.2 C134.2 C135.2 C136.2 C137.2 C138.2 C141.2 C142.2 C143.2 C144.2 C145.2 C146.2 C147.2 C148.2 C149.2 C150.2 C151.2 C152.2 C153.2 C154.2 C212.2 C213.2 C214.2 C216.2 C217.2 C218.2 DC_IN1.3 DC_IN1.4(GND1) M1.1 M2.1 M3.1 M4.1 R66.1 R67.1 R68.1 R70.2 R71.1 R72.1 R73.2 R135.2 U1.A4(GND_3) U1.A8(GND_4) U1.A13(GND_1) U1.A25(GND_2) U1.AA7(GND_10) U1.AA10(GND_5) U1.AA13(GND_6) U1.AA16(GND_7) U1.AA19(GND_8) U1.AA22(GND_9) U1.AB3(GND_12) U1.AB24(GND_11) U1.AD4(GND_18) U1.AD7(GND_19) U1.AD10(GND_13) U1.AD13(GND_14) U1.AD16(GND_15) U1.AD19(GND_16) U1.AD22(GND_17) U1.AE1(GND_20) U1.AE25(GND_21) U1.B4(GND_22) U1.C1(GND_23) U1.C4(GND_25) U1.C6(GND_26) U1.C10(GND_24) U1.D3(GND_27) U1.D6(GND_28) U1.D8(GND_29) U1.E5(GND_30) U1.E6(GND_31) U1.E7(GND_32) U1.F5(GND_33) U1.F6(GND_34) U1.F7(GND_35) U1.F8(GND_36) U1.G3(GND_39) U1.G10(GND_37) U1.G19(GND_38) U1.H8(GND_43) U1.H12(GND_40) U1.H15(GND_41) U1.H18(GND_42) U1.J2(GND_47) U1.J8(GND_48) U1.J12(GND_44) U1.J15(GND_45) U1.J18(GND_46) U1.K8(GND_53) U1.K10(GND_49) U1.K12(GND_50) U1.K15(GND_51) U1.K18(GND_52) U1.L2(GND_58) U1.L5(GND_59) U1.L8(GND_60) U1.L10(GND_54) U1.L12(GND_55) U1.L15(GND_56) U1.L18(GND_57) U1.M8(GND_65) U1.M10(GND_61) U1.M12(GND_62) U1.M15(GND_63) U1.M18(GND_64) U1.N8(GND_69) U1.N10(GND_66) U1.N15(GND_67) U1.N18(GND_68) U1.P8(GND_74) U1.P10(GND_70) U1.P12(GND_71) U1.P15(GND_72) U1.P18(GND_73) U1.R8(GND_78) U1.R12(GND_75) U1.R15(GND_76) U1.R17(GND_77) U1.T8(GND_84) U1.T11(GND_79) U1.T12(GND_80) U1.T15(GND_81) U1.T17(GND_82) U1.T19(GND_83) U1.U8(GND_89) U1.U11(GND_85) U1.U12(GND_86) U1.U15(GND_87) U1.U17(GND_88) U1.U19(GND_90) U1.V8(GND_91) U1.V19(GND_92) U1.W3(GND_93) U1.W7(GND_94) U1.W8(GND_95) U1.W9(GND_96) U1.W10(GND_97) U1.W11(GND_98) U1.W12(GND_99) U1.W13(GND_100) U1.W15(GND_101) U1.W16(GND_102) U1.W17(GND_103) U1.W18(GND_104) U1.W19(GND_105) U1.Y5(GND_106) U1.Y24(GND_107) U2.A9(VSS1) U2.B1(VSSQ1) U2.B3(VSS2) U2.B9(VSSQ2) U2.D1(VSSQ3) U2.D8(VSSQ4) U2.E1(VSS3) U2.E2(VSSQ5) U2.E8(VSSQ6) U2.F9(VSSQ7) U2.G1(VSSQ8) U2.G8(VSS4) U2.G9(VSSQ9) U2.J2(VSS5) U2.J8(VSS6) U2.M1(VSS7) U2.M9(VSS8) U2.P1(VSS9) U2.P9(VSS10) U2.T1(VSS11) U2.T9(VSS12) U3.A9(VSS1) U3.B1(VSSQ1) U3.B3(VSS2) U3.B9(VSSQ2) U3.D1(VSSQ3) U3.D8(VSSQ4) U3.E1(VSS3) U3.E2(VSSQ5) U3.E8(VSSQ6) U3.F9(VSSQ7) U3.G1(VSSQ8) U3.G8(VSS4) U3.G9(VSSQ9) U3.J2(VSS5) U3.J8(VSS6) U3.M1(VSS7) U3.M9(VSS8) U3.P1(VSS9) U3.P9(VSS10) U3.T1(VSS11) U3.T9(VSS12) U4.A9(VSS1) U4.B1(VSSQ1) U4.B3(VSS2) U4.B9(VSSQ2) U4.D1(VSSQ3) U4.D8(VSSQ4) U4.E1(VSS3) U4.E2(VSSQ5) U4.E8(VSSQ6) U4.F9(VSSQ7) U4.G1(VSSQ8) U4.G8(VSS4) U4.G9(VSSQ9) U4.J2(VSS5) U4.J8(VSS6) U4.M1(VSS7) U4.M9(VSS8) U4.P1(VSS9) U4.P9(VSS10) U4.T1(VSS11) U4.T9(VSS12) U5.A9(VSS1) U5.B1(VSSQ1) U5.B3(VSS2) U5.B9(VSSQ2) U5.D1(VSSQ3) U5.D8(VSSQ4) U5.E1(VSS3) U5.E2(VSSQ5) U5.E8(VSSQ6) U5.F9(VSSQ7) U5.G1(VSSQ8) U5.G8(VSS4) U5.G9(VSSQ9) U5.J2(VSS5) U5.J8(VSS6) U5.M1(VSS7) U5.M9(VSS8) U5.P1(VSS9) U5.P9(VSS10) U5.T1(VSS11) U5.T9(VSS12) U15.G1(GND)
VDD_1V5: C80.1 C87.1 C88.1 C89.1 C90.1 C91.1 C92.1 C93.1 C94.1 C95.1 C96.1 C97.1 C98.1 C99.1 C100.1 C101.1 C102.1 C103.1 C104.1 C105.1 C106.1 C107.1 C108.1 C109.1 C111.1 C112.1 C113.1 C114.1 C115.1 C116.1 C117.1 C118.1 C119.1 C120.1 C121.1 C122.1 C123.1 C124.1 C125.1 C126.1 C127.1 C128.1 C129.1 C130.1 C131.1 C132.1 C133.1 C134.1 C135.1 C136.1 C137.1 C138.1 C140.1 C141.1 C142.1 C143.1 C144.1 C145.1 C146.1 C147.1 C148.1 C149.1 C150.1 C151.1 C152.1 C153.1 C154.1 C215.1 C216.1 C217.1 C218.1 L6.2 R69.1 R133.1 U1.R18(NVCC_DRAM_1) U1.T18(NVCC_DRAM_2) U1.U18(NVCC_DRAM_3) U1.V9(NVCC_DRAM_13) U1.V10(NVCC_DRAM_4) U1.V11(NVCC_DRAM_5) U1.V12(NVCC_DRAM_6) U1.V13(NVCC_DRAM_7) U1.V14(NVCC_DRAM_8) U1.V15(NVCC_DRAM_9) U1.V16(NVCC_DRAM_10) U1.V17(NVCC_DRAM_11) U1.V18(NVCC_DRAM_12) U2.A1(VDDQ1) U2.A8(VDDQ2) U2.B2(VDD1) U2.C1(VDDQ3) U2.C9(VDDQ4) U2.D2(VDDQ5) U2.D9(VDD2) U2.E9(VDDQ6) U2.F1(VDDQ7) U2.G7(VDD3) U2.H2(VDDQ8) U2.H9(VDDQ9) U2.K2(VDD4) U2.K8(VDD5) U2.N1(VDD6) U2.N9(VDD7) U2.R1(VDD8) U2.R9(VDD9) U3.A1(VDDQ1) U3.A8(VDDQ2) U3.B2(VDD1) U3.C1(VDDQ3) U3.C9(VDDQ4) U3.D2(VDDQ5) U3.D9(VDD2) U3.E9(VDDQ6) U3.F1(VDDQ7) U3.G7(VDD3) U3.H2(VDDQ8) U3.H9(VDDQ9) U3.K2(VDD4) U3.K8(VDD5) U3.N1(VDD6) U3.N9(VDD7) U3.R1(VDD8) U3.R9(VDD9) U4.A1(VDDQ1) U4.A8(VDDQ2) U4.B2(VDD1) U4.C1(VDDQ3) U4.C9(VDDQ4) U4.D2(VDDQ5) U4.D9(VDD2) U4.E9(VDDQ6) U4.F1(VDDQ7) U4.G7(VDD3) U4.H2(VDDQ8) U4.H9(VDDQ9) U4.K2(VDD4) U4.K8(VDD5) U4.N1(VDD6) U4.N9(VDD7) U4.R1(VDD8) U4.R9(VDD9) U5.A1(VDDQ1) U5.A8(VDDQ2) U5.B2(VDD1) U5.C1(VDDQ3) U5.C9(VDDQ4) U5.D2(VDDQ5) U5.D9(VDD2) U5.E9(VDDQ6) U5.F1(VDDQ7) U5.G7(VDD3) U5.H2(VDDQ8) U5.H9(VDDQ9) U5.K2(VDD4) U5.K8(VDD5) U5.N1(VDD6) U5.N9(VDD7) U5.R1(VDD8) U5.R9(VDD9)
DDR_VREF: C76.1 C77.1 C78.1 C79.1 C80.2 C81.1 C82.1 C83.1 C84.1 C85.1 C86.1 R69.2 R70.1 U1.AC2(DRAM_VREF) U2.H1(VREFDQ) U2.M8(VREFCA) U3.H1(VREFDQ) U3.M8(VREFCA) U4.H1(VREFDQ) U4.M8(VREFCA) U5.H1(VREFDQ) U5.M8(VREFCA)
DRAM0_ZQ: R66.2 U2.L8(ZQ)
DRAM1_ZQ: R67.2 U3.L8(ZQ)
DRAM2_ZQ: R71.2 U4.L8(ZQ)
DRAM3_ZQ: R72.2 U5.L8(ZQ)
DRAM_A0: U1.AC14(DRAM_A0) U2.N3(A0) U3.N3(A0) U4.N3(A0) U5.N3(A0)
DRAM_A1: U1.AB14(DRAM_A1) U2.P7(A1) U3.P7(A1) U4.P7(A1) U5.P7(A1)
DRAM_A2: U1.AA14(DRAM_A2) U2.P3(A2) U3.P3(A2) U4.P3(A2) U5.P3(A2)
DRAM_A3: U1.Y14(DRAM_A3) U2.N2(A3) U3.N2(A3) U4.N2(A3) U5.N2(A3)
DRAM_A4: U1.W14(DRAM_A4) U2.P8(A4) U3.P8(A4) U4.P8(A4) U5.P8(A4)
DRAM_A5: U1.AE13(DRAM_A5) U2.P2(A5) U3.P2(A5) U4.P2(A5) U5.P2(A5)
DRAM_A6: U1.AC13(DRAM_A6) U2.R8(A6) U3.R8(A6) U4.R8(A6) U5.R8(A6)
DRAM_A7: U1.Y13(DRAM_A7) U2.R2(A7) U3.R2(A7) U4.R2(A7) U5.R2(A7)
DRAM_A8: U1.AB13(DRAM_A8) U2.T8(A8) U3.T8(A8) U4.T8(A8) U5.T8(A8)
DRAM_A9: U1.AE12(DRAM_A9) U2.R3(A9) U3.R3(A9) U4.R3(A9) U5.R3(A9)
DRAM_A10: U1.AA15(DRAM_A10) U2.L7(A10/AP) U3.L7(A10/AP) U4.L7(A10/AP) U5.L7(A10/AP)
DRAM_A11: U1.AC12(DRAM_A11) U2.R7(A11) U3.R7(A11) U4.R7(A11) U5.R7(A11)
DRAM_A12: U1.AD12(DRAM_A12) U2.N7(A12/~{BC}) U3.N7(A12/~{BC}) U4.N7(A12/~{BC}) U5.N7(A12/~{BC})
DRAM_A13: U1.AC17(DRAM_A13) U2.T3(A13) U3.T3(A13) U4.T3(A13) U5.T3(A13)
DRAM_A14: U1.AA12(DRAM_A14) U2.T7(NC) U3.T7(NC) U4.T7(NC) U5.T7(NC)
DRAM_A15: U1.Y12(DRAM_A15) U2.M7(NC) U3.M7(NC) U4.M7(NC) U5.M7(NC)
DRAM_CAS_B: U1.AE16(DRAM_CAS) U2.K3(~{CAS}) U3.K3(~{CAS}) U4.K3(~{CAS}) U5.K3(~{CAS})
DRAM_CS0_B: U1.Y16(DRAM_CS0) U2.L2(~{CS}) U3.L2(~{CS}) U4.L2(~{CS}) U5.L2(~{CS})
DRAM_CS1_B: TP2.1 U1.AD17(DRAM_CS1)
DRAM_D0: U1.AD2(DRAM_D0) U2.E3(DQ0)
DRAM_D1: U1.AE2(DRAM_D1) U2.F8(DQ3)
DRAM_D2: U1.AC4(DRAM_D2) U2.G2(DQ6)
DRAM_D3: U1.AA5(DRAM_D3) U2.H3(DQ4)
DRAM_D4: U1.AC1(DRAM_D4) U2.F2(DQ2)
DRAM_D5: U1.AD1(DRAM_D5) U2.F7(DQ1)
DRAM_D6: U1.AB4(DRAM_D6) U2.H7(DQ7)
DRAM_D7: U1.AE4(DRAM_D7) U2.H8(DQ5)
DRAM_D8: U1.AD5(DRAM_D8) U2.D7(DQ8)
DRAM_D9: U1.AE5(DRAM_D9) U2.A7(DQ12)
DRAM_D10: U1.AA6(DRAM_D10) U2.C2(DQ11)
DRAM_D11: U1.AE7(DRAM_D11) U2.B8(DQ14)
DRAM_D12: U1.AB5(DRAM_D12) U2.A2(DQ13)
DRAM_D13: U1.AC5(DRAM_D13) U2.A3(DQ15)
DRAM_D14: U1.AB6(DRAM_D14) U2.C3(DQ9)
DRAM_D15: U1.AC7(DRAM_D15) U2.C8(DQ10)
DRAM_D16: U1.AB7(DRAM_D16) U3.D7(DQ8)
DRAM_D17: U1.AA8(DRAM_D17) U3.C8(DQ10)
DRAM_D18: U1.AB9(DRAM_D18) U3.C2(DQ11)
DRAM_D19: U1.Y9(DRAM_D19) U3.A2(DQ13)
DRAM_D20: U1.Y7(DRAM_D20) U3.A7(DQ12)
DRAM_D21: U1.Y8(DRAM_D21) U3.B8(DQ14)
DRAM_D22: U1.AC8(DRAM_D22) U3.C3(DQ9)
DRAM_D23: U1.AA9(DRAM_D23) U3.A3(DQ15)
DRAM_D24: U1.AE9(DRAM_D24) U3.E3(DQ0)
DRAM_D25: U1.Y10(DRAM_D25) U3.F8(DQ3)
DRAM_D26: U1.AE11(DRAM_D26) U3.H3(DQ4)
DRAM_D27: U1.AB11(DRAM_D27) U3.G2(DQ6)
DRAM_D28: U1.AC9(DRAM_D28) U3.F7(DQ1)
DRAM_D29: U1.AD9(DRAM_D29) U3.F2(DQ2)
DRAM_D30: U1.AD11(DRAM_D30) U3.H7(DQ7)
DRAM_D31: U1.AC11(DRAM_D31) U3.H8(DQ5)
DRAM_D32: U1.AA17(DRAM_D32) U4.E3(DQ0)
DRAM_D33: U1.AA18(DRAM_D33) U4.G2(DQ6)
DRAM_D34: U1.AC18(DRAM_D34) U4.H8(DQ5)
DRAM_D35: U1.AE19(DRAM_D35) U4.F2(DQ2)
DRAM_D36: U1.Y17(DRAM_D36) U4.H3(DQ4)
DRAM_D37: U1.Y18(DRAM_D37) U4.H7(DQ7)
DRAM_D38: U1.AB19(DRAM_D38) U4.F8(DQ3)
DRAM_D39: U1.AC19(DRAM_D39) U4.F7(DQ1)
DRAM_D40: U1.Y19(DRAM_D40) U4.D7(DQ8)
DRAM_D41: U1.AB20(DRAM_D41) U4.A3(DQ15)
DRAM_D42: U1.AB21(DRAM_D42) U4.C8(DQ10)
DRAM_D43: U1.AD21(DRAM_D43) U4.C3(DQ9)
DRAM_D44: U1.Y20(DRAM_D44) U4.A2(DQ13)
DRAM_D45: U1.AA20(DRAM_D45) U4.B8(DQ14)
DRAM_D46: U1.AE21(DRAM_D46) U4.C2(DQ11)
DRAM_D47: U1.AC21(DRAM_D47) U4.A7(DQ12)
DRAM_D48: U1.AC22(DRAM_D48) U5.D7(DQ8)
DRAM_D49: U1.AE22(DRAM_D49) U5.A7(DQ12)
DRAM_D50: U1.AE24(DRAM_D50) U5.A3(DQ15)
DRAM_D51: U1.AC24(DRAM_D51) U5.C3(DQ9)
DRAM_D52: U1.AB22(DRAM_D52) U5.B8(DQ14)
DRAM_D53: U1.AC23(DRAM_D53) U5.C8(DQ10)
DRAM_D54: U1.AD25(DRAM_D54) U5.A2(DQ13)
DRAM_D55: U1.AC25(DRAM_D55) U5.C2(DQ11)
DRAM_D56: U1.AB25(DRAM_D56) U5.E3(DQ0)
DRAM_D57: U1.AA21(DRAM_D57) U5.F8(DQ3)
DRAM_D58: U1.Y25(DRAM_D58) U5.G2(DQ6)
DRAM_D59: U1.Y22(DRAM_D59) U5.H8(DQ5)
DRAM_D60: U1.AB23(DRAM_D60) U5.F7(DQ1)
DRAM_D61: U1.AA23(DRAM_D61) U5.H7(DQ7)
DRAM_D62: U1.Y23(DRAM_D62) U5.F2(DQ2)
DRAM_D63: U1.W25(DRAM_D63) U5.H3(DQ4)
DRAM_DQM0: U1.AC3(DRAM_DQM0) U2.E7(LDM)
DRAM_DQM1: U1.AC6(DRAM_DQM1) U2.D3(UDM)
DRAM_DQM2: U1.AB8(DRAM_DQM2) U3.D3(UDM)
DRAM_DQM3: U1.AE10(DRAM_DQM3) U3.E7(LDM)
DRAM_DQM4: U1.AB18(DRAM_DQM4) U4.E7(LDM)
DRAM_DQM5: U1.AC20(DRAM_DQM5) U4.D3(UDM)
DRAM_DQM6: U1.AD24(DRAM_DQM6) U5.D3(UDM)
DRAM_DQM7: U1.Y21(DRAM_DQM7) U5.E7(LDM)
DRAM_RAS_B: U1.AB15(DRAM_RAS) U2.J3(~{RAS}) U3.J3(~{RAS}) U4.J3(~{RAS}) U5.J3(~{RAS})
DRAM_RESET_B: R68.2 U1.Y6(DRAM_RESET) U2.T2(~{RESET}) U3.T2(~{RESET}) U4.T2(~{RESET}) U5.T2(~{RESET})
DRAM_SDBA0: U1.AC15(DRAM_SDBA0) U2.M2(BA0) U3.M2(BA0) U4.M2(BA0) U5.M2(BA0)
DRAM_SDBA1: U1.Y15(DRAM_SDBA1) U2.N8(BA1) U3.N8(BA1) U4.N8(BA1) U5.N8(BA1)
DRAM_SDBA2: U1.AB12(DRAM_SDBA2) U2.M3(BA2) U3.M3(BA2) U4.M3(BA2) U5.M3(BA2)
DRAM_SDCKE0: U1.Y11(DRAM_SDCKE0) U2.K9(CKE) U3.K9(CKE) U4.K9(CKE) U5.K9(CKE)
DRAM_SDCKE1: U1.AA11(DRAM_SDCKE1)
DRAM_SDCLK0: R76.1 U1.AD15(DRAM_SDCLK_0) U2.J7(CK) U3.J7(CK) U4.J7(CK) U5.J7(CK)
DRAM_SDCLK0_B: R78.2 U1.AE15(DRAM_SDCLK_0_B) U2.K7(~{CK}) U3.K7(~{CK}) U4.K7(~{CK}) U5.K7(~{CK})
DRAM_SDODT0: U1.AC16(DRAM_SDODT0) U2.K1(ODT) U3.K1(ODT) U4.K1(ODT) U5.K1(ODT)
DRAM_SDODT1: U1.AB17(DRAM_SDODT1)
DRAM_SDQS0: U1.AE3(DRAM_SDQS0) U2.F3(LDQS)
DRAM_SDQS0_B: U1.AD3(DRAM_SDQS0_B) U2.G3(~{LDQS})
DRAM_SDQS1: U1.AD6(DRAM_SDQS1) U2.C7(UDQS)
DRAM_SDQS1_B: U1.AE6(DRAM_SDQS1_B) U2.B7(~{UDQS})
DRAM_SDQS2: U1.AD8(DRAM_SDQS2) U3.C7(UDQS)
DRAM_SDQS2_B: U1.AE8(DRAM_SDQS2_B) U3.B7(~{UDQS})
DRAM_SDQS3: U1.AC10(DRAM_SDQS3) U3.F3(LDQS)
DRAM_SDQS3_B: U1.AB10(DRAM_SDQS3_B) U3.G3(~{LDQS})
DRAM_SDQS4: U1.AD18(DRAM_SDQS4) U4.F3(LDQS)
DRAM_SDQS4_B: U1.AE18(DRAM_SDQS4_B) U4.G3(~{LDQS})
DRAM_SDQS5: U1.AD20(DRAM_SDQS5) U4.C7(UDQS)
DRAM_SDQS5_B: U1.AE20(DRAM_SDQS5_B) U4.B7(~{UDQS})
DRAM_SDQS6: U1.AD23(DRAM_SDQS6) U5.C7(UDQS)
DRAM_SDQS6_B: U1.AE23(DRAM_SDQS6_B) U5.B7(~{UDQS})
DRAM_SDQS7: U1.AA25(DRAM_SDQS7) U5.F3(LDQS)
DRAM_SDQS7_B: U1.AA24(DRAM_SDQS7_B) U5.G3(~{LDQS})
DRAM_WE_B: U1.AB16(DRAM_SDWE) U2.L3(~{WE}) U3.L3(~{WE}) U4.L3(~{WE}) U5.L3(~{WE})
ZQPAD: R73.1 U1.AE17(ZQPAD)
N29831394: C140.2 R76.2 R78.1
N31313342: C212.1 C213.1 C214.1 DC_IN1.5 R132.1 U15.8(SVIN) U15.9(PVIN0) U15.10(PVIN1)
N31313358: L6.1 U15.1(LX0) U15.2(LX1) U15.3(LX2)
N31313368: C215.2 R133.2 R135.1 U15.6(FB)
N31313399: TP11.1 U15.4(PGOOD)
N31313405: R132.2 U15.5(Enable)

Not connected (* = marked no-connect by the designer): U1 A5(FA_ANA)* AD14(DRAM_SDCLK_1)* AE14(DRAM_SDCLK_1_B)* B5(VDD_FA)* C8(GPANAIO)* E8(NVCC_PLL_OUT)* G9(VDD_SNVS_CAP)* G11(VDD_SNVS_IN)* G14(NVCC_SD3)* G15(NVCC_NANDF)* G16(NVCC_SD1)* G17(NVCC_SD2)* G18(NVCC_RGMII)* H9(VDDHIGH_IN_1)* H10(VDDHIGH_CAP_1)* H11(VDDARM23_CAP_1)* H13(VDDARM_CAP_1)* H14(VDDARM_IN_1)* H16(VDDSOC_IN_1)* H17(VDDPU_CAP_1)* J7(NVCC_JTAG)* J9(VDDHIGH_IN_2)* J10(VDDHIGH_CAP_2)* J11(VDDARM23_CAP_2)* J13(VDDARM_CAP_2)* J14(VDDARM_IN_2)* J16(VDDSOC_IN_2)* J17(VDDPU_CAP_2)* K7(NVCC_MIPI)* K9(VDDARM23_IN_1)* K11(VDDARM23_CAP_3)* K13(VDDARM_CAP_3)* K14(VDDARM_IN_3)* K16(VDDSOC_IN_3)* K17(VDDPU_CAP_3)* K19(NVCC_EIM0)* L9(VDDARM23_IN_2)* L11(VDDARM23_CAP_4)* L13(VDDARM_CAP_4)* L14(VDDARM_IN_4)* L16(VDDSOC_IN_4)* L17(VDDPU_CAP_4)* L19(NVCC_EIM1)* M9(VDDARM23_IN_3)* M11(VDDARM23_CAP_5)* M13(VDDARM_CAP_5)* M14(VDDARM_IN_5)* M16(VDDSOC_IN_5)* M17(VDDPU_CAP_5)* M19(NVCC_EIM2)* N7(NVCC_CSI)* N9(VDDARM23_IN_4)* N11(VDDARM23_CAP_6)* N12(VDD_CACHE_CAP)* N13(VDDARM_CAP_6)* N14(VDDARM_IN_6)* N16(VDDSOC_IN_6)* N17(VDDPU_CAP_6)* P7(NVCC_GPIO)* P9(VDDARM23_IN_5)* P11(VDDARM23_CAP_7)* P13(VDDARM_CAP_7)* P14(VDDARM_IN_7)* P16(VDDSOC_IN_7)* P17(VDDPU_CAP_7)* P19(NVCC_LCD)* R9(VDDARM23_IN_6)* R10(VDDSOC_CAP_1)* R11(VDDARM23_CAP_8)* R13(VDDARM_CAP_8)* R14(VDDARM_IN_8)* R16(VDDSOC_IN_8)* R19(NVCC_ENET)* T9(VDDARM23_IN_7)* T10(VDDSOC_CAP_2)* T13(VDDSOC_CAP_3)* T14(VDDSOC_CAP_4)* T16(VDDSOC_IN_9)* U9(VDDARM23_IN_8)* U10(VDDSOC_CAP_5)* U13(VDDSOC_CAP_6)* U14(VDDSOC_CAP_7)* U16(VDDSOC_IN_10)*; U2 J1(NC)* J9(NC)* L1(NC)* L9(NC)*; U3 J1(NC)* J9(NC)* L1(NC)* L9(NC)*; U4 J1(NC)* J9(NC)* L1(NC)* L9(NC)*; U5 J1(NC)* J9(NC)* L1(NC)* L9(NC)*; U15 7(NC)*

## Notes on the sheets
sheet 1
- FB=0.6V
sheet 2
- 1 GByte
  DDR3
